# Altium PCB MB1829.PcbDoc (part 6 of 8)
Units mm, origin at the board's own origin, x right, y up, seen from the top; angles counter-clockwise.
Board outline 90 x 110 mm, 6 copper layers (Top Layer, Signal Layer 1, Signal Layer 2, Signal Layer 3, Signal Layer 4, Bottom Layer), stack 1.578 mm thick; 466 components, 354 nets, 2058 pads, 1522 vias.
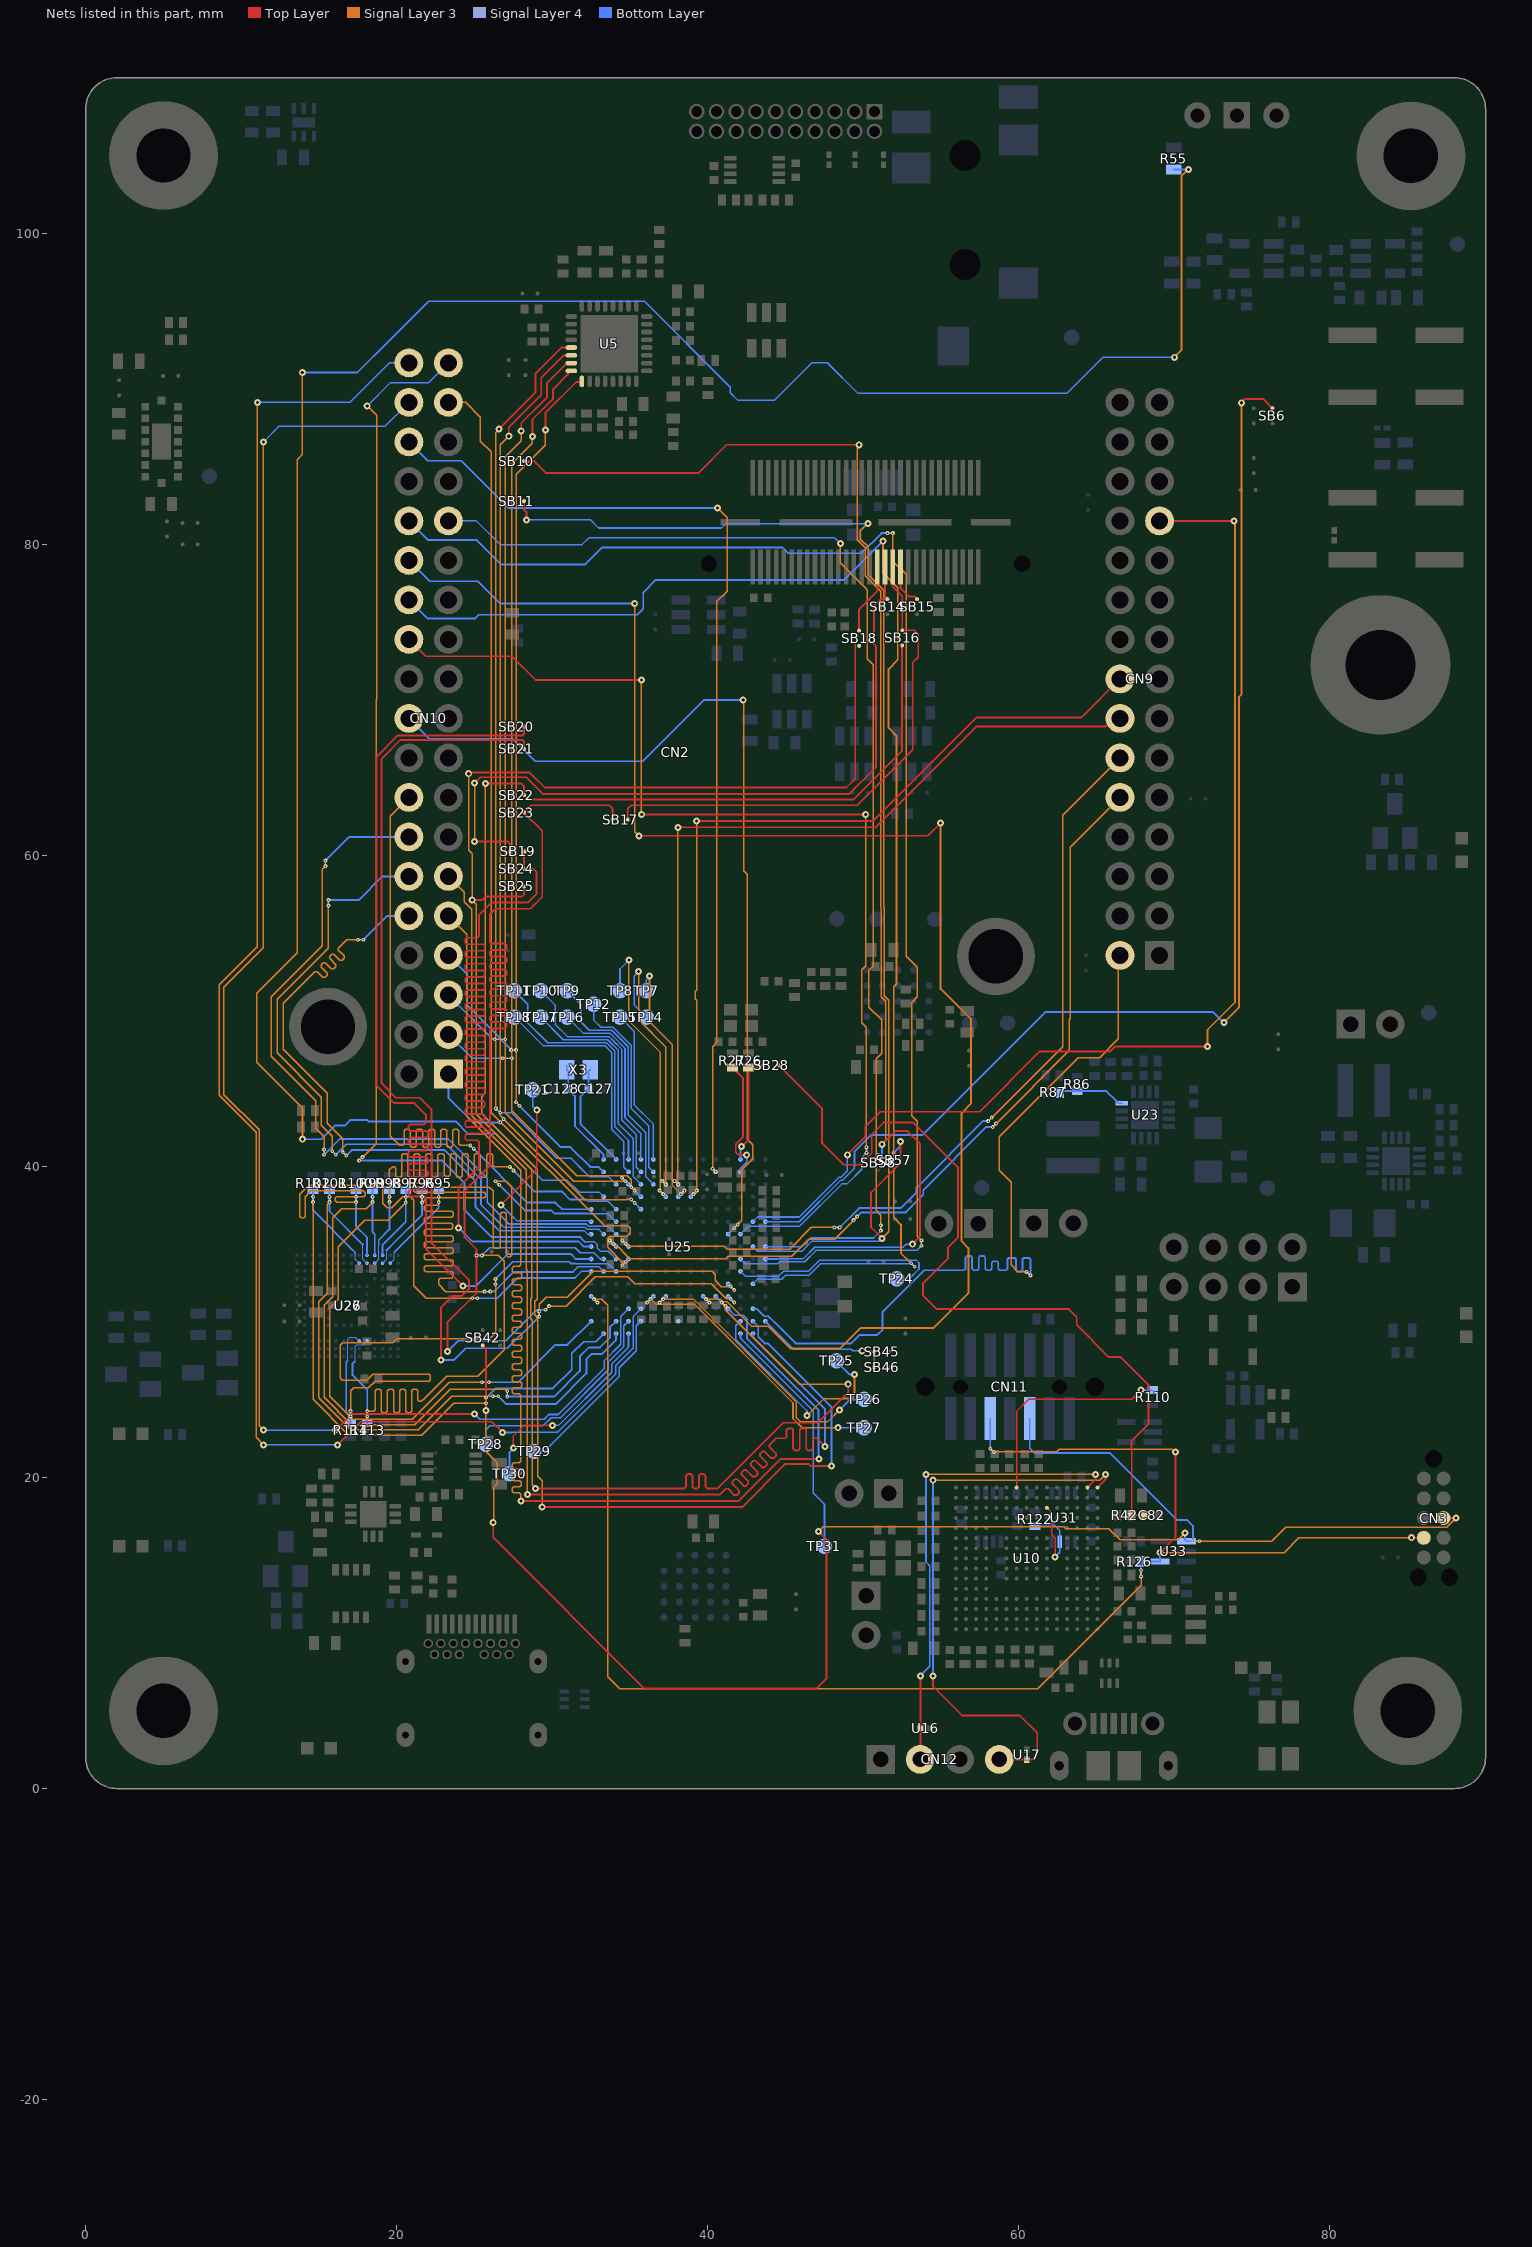
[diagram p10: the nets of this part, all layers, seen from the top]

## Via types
v1: diameter 0.45, hole 0.2, Top Layer to Bottom Layer, tented both sides, 1062 vias
v2: diameter 0.25, hole 0.1, Signal Layer 4 to Bottom Layer, tented both sides, 274 vias
v3: diameter 0.25, hole 0.1, Signal Layer 3 to Signal Layer 4, tented both sides, 119 vias
v4: diameter 0.25, hole 0.1, Top Layer to Signal Layer 1, tented both sides, 47 vias
v5: diameter 0.25, hole 0.1, Signal Layer 1 to Signal Layer 2, tented both sides, 20 vias

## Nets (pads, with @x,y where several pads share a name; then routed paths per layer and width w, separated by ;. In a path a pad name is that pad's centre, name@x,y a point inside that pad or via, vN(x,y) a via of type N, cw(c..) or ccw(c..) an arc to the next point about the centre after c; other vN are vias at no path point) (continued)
PB12: SB21.1 U25.M11 | length 76.1
  Top Layer w0.12: v1(22.85,27.55) 22.85,30.933 23.592,31.675 24.175,31.675 24.65,32.15 24.65,32.675 22.225,35.1 22.225,43.67 21.476,44.419 19.943,44.419 19.025,45.338 19.025,66.21 20.24,67.425 28.075,67.425 28.175,67.325 SB21.1@28.175,66.85
  Signal Layer 3 w0.09: v3(29.15,30.675) 29.15,31.15 29.6,31.6 30.975,31.6 32.625,33.25 40.275,33.25 40.475,33.05 40.475,32.675 40.875,32.275 v3(41.475,32.275)
  Signal Layer 4 w0.1: v2(29.15,30.35) v3@29.15,30.683 ; v3(41.475,32.275) v2(41.7,32.05)
  Bottom Layer w0.12: v1(22.85,27.55) 23.675,27.55 24.252,28.128 ; 24.255,28.125 24.445,28.315 27.115,28.315 v2(29.15,30.35) ; U25.M11@41.3,32.45 v2(41.7,32.05)
PB13: SB17.2 SB23.1 U25.M12 | length 81.3
  Top Layer w0.12: v1(23.25,28.1) 23.25,29.97 25.125,31.845 25.125,34.675 24.36,35.44 24.36,38.449 25.995,40.084 25.995,47.47 25.995,48.288 25.995,48.768 26.1,48.873 26.96,48.873 27.065,48.978 27.065,49.188 26.96,49.293 26.098,49.293 25.993,49.398 25.993,49.608 26.098,49.713 26.96,49.713 27.065,49.818 27.065,50.028 26.96,50.133 26.098,50.133 25.993,50.238 25.993,50.448 26.098,50.553 26.96,50.553 27.065,50.658 27.065,50.868 26.96,50.973 26.098,50.973 25.993,51.078 25.993,51.288 26.098,51.393 26.96,51.393 27.065,51.498 27.065,51.708 26.96,51.813 26.098,51.813 25.993,51.918 25.993,52.128 26.098,52.233 26.96,52.233 27.065,52.338 27.065,52.548 26.96,52.653 26.098,52.653 25.993,52.758 25.993,52.968 26.098,53.073 26.96,53.073 27.065,53.178 27.065,53.388 26.96,53.493 26.098,53.493 25.993,53.598 25.993,53.808 26.098,53.913 26.96,53.913 27.065,54.018 27.065,54.228 26.96,54.333 26.1,54.333 25.995,54.438 25.995,54.847 25.995,56.21 26.351,56.566 28.591,56.566 29.35,57.325 29.35,61.575 SB23.1@28.175,62.75 28.65,63.225 33.65,63.225 33.875,63 SB17.2@33.875,62.3
  Signal Layer 3 w0.09: v3(29.794,31.024) 30.899,31.024 32.775,32.9 34.85,32.9 35.3,32.45 40.23,32.45 41.18,31.5 41.45,31.5 v3(41.475,31.475)
  Signal Layer 4 w0.1: v2(29.556,30.787) v3(29.794,31.024) ; v3(41.475,31.475) v2(41.7,31.25)
  Bottom Layer w0.12: v1(23.25,28.1) 23.94,28.79 27,28.79 28.997,30.787 v2(29.556,30.787) ; U25.M12@41.3,31.65 v2(41.7,31.25)
PB14: CN9.2 U25.P13 | length 54.6
  Signal Layer 3 w0.09: v3(60.49,33.225) 59.935,33.225 59.495,33.665 59.495,38.985 58.725,39.755 58.725,41.91 63.805,46.99 65.185,46.99 66.4,48.205 66.4,53.464 CN9.2@66.5,53.564
  Signal Layer 4 w0.1: v3(60.49,33.225) 60.502,33.225 60.727,33 v2(60.74,33)
  Bottom Layer w0.1: U25.P13@42.9,30.85 43.15,30.85 43.625,30.375 43.89,30.375 44.29,29.975 44.29,29.97
  Bottom Layer w0.12: 44.29,29.97 45.64,28.62 49.22,28.62 49.77,29.17 50.895,29.17 51.235,29.51 51.235,30.62 ; 51.227,30.628 53.925,33.325 56.41,33.325 56.47,33.325 56.575,33.43 56.575,34.145 56.68,34.25 56.89,34.25 56.995,34.145 56.995,33.427 57.1,33.322 57.31,33.322 57.415,33.427 57.415,34.145 57.52,34.25 57.73,34.25 57.835,34.145 57.835,33.427 57.94,33.322 58.15,33.322 58.255,33.427 58.255,33.8 58.36,33.905 58.57,33.905 58.675,33.8 58.675,33.43 58.78,33.325 59.061,33.325 59.16,33.325 59.27,33.435 59.27,34.04 59.345,34.115 59.73,34.115 59.805,34.04 59.805,33.335 59.885,33.255 60.17,33.255 60.24,33.325 60.24,34.04 60.315,34.115 60.655,34.115 60.74,34.03 v2(60.74,33)
PB15: SB45.2 SB46.2 U25.R14 | length 8.8
  Top Layer w0.12: v1(49.925,28.15) 50.65,28.15 SB45.2@50.7,28.1 SB46.2@50.7,27.075
  Bottom Layer w0.12: U25.R14@43.7,30.05 45.5,28.25 49.225,28.25 49.325,28.15 v1(49.925,28.15)
PC4: SB6.1 U25.R6 | length 78.6
  Top Layer w0.12: v1(74.31,89.1) 74.56,89.35 75.7,89.35 SB6.1@76.3,88.75
  Signal Layer 3 w0.12: v1(73.175,49.249) 74.14,50.214 74.14,70.179 74.31,70.349 v1(74.31,89.1)
  Bottom Layer w0.1: U25.R6@43.7,36.45 45.875,36.45 48.525,39.1 48.638,39.1 49.425,39.887 49.425,40.025
  Bottom Layer w0.12: 49.425,40.025 49.425,40.95 50.506,42.031 53.806,42.031 61.7,49.925 72.499,49.925 v1(73.175,49.249)
PC5: CN9.23 U25.P6 | length 74.2
  Top Layer w0.12: v1(48.975,40.75) 50.125,41.9 50.125,42.55 51.093,43.518 57.468,43.518 61.348,47.398 65.884,47.398 66.207,47.721 v1(72.125,47.721) ; CN9.23@69.04,81.504 v1(73.825,81.504)
  Signal Layer 3 w0.12: v1(72.125,47.721) 72.125,48.781 73.885,50.541 73.885,81.444 v1(73.825,81.504)
  Bottom Layer w0.1: U25.P6@42.9,36.45 43.2,36.75 45.875,36.75 48.425,39.3 48.555,39.3 48.975,39.72 v1(48.975,40.75)
PC14-OSC32_IN: C128.1 U25.B1 X3.2 | length 7
  Bottom Layer w0.12: X3.2@30.925,46.5 X3.2@30.925,46.225 31.025,46.125 31.025,44.95 31.45,44.525 31.45,42.6 33.3,40.75 U25.B1@33.3,40.45
PC15-OSC32_OUT: C127.1 U25.C1 X3.1 | length 7
  Bottom Layer w0.12: X3.1@32.425,46.225 32.325,46.125 C127.1@32.325,45 31.81,44.485 31.81,42.749 34.1,40.459 U25.C1@34.1,40.45
PD0: CN10.35 U25.D9 | length 64.4
  Signal Layer 3 w0.09: CN10.35@23.32,89.124 24.426,89.124 25.375,88.175 25.375,86.638 26.075,85.938 26.075,43.468 33.368,36.175 34.85,36.175 35,36.025 35,35.7 34.8,35.5 33.7,35.5 33.55,35.35 33.55,34.8 34.475,33.875 v3(34.725,33.875)
  Signal Layer 4 w0.1: v2(34.5,33.65) v3(34.725,33.875)
  Bottom Layer w0.12: v2(34.5,33.65) U25.D9@34.9,34.05
PD1: CN10.37 U25.C9 | length 75.9
  Signal Layer 3 w0.09: v3(17.8,40.6) 18.666,41.466 18.666,41.539 ; v1(18.1,88.9) 18.7,88.3 18.7,70.04 18.665,70.005 18.665,41.54
  Signal Layer 4 w0.1: v2(17.575,40.375) v3(17.8,40.6)
  Bottom Layer w0.1: v1(18.1,88.9) 19.6,90.4 22.056,90.4 CN10.37@23.32,91.664 ; 32.125,35.15 32.717,35.15 32.875,34.992 32.875,34.775 33.1,34.55 33.6,34.55 U25.C9@34.1,34.05
  Bottom Layer w0.12: v2(17.575,40.375) 22.925,40.375 24.345,38.955 24.345,37.215 26.1,35.46 31.805,35.46 32.125,35.14
PD3: SB20.1 U25.A9 | length 70.2
  Top Layer w0.12: v1(24.25,32.325) 21.875,34.7 21.875,37.914 21.875,37.974 21.77,38.079 20.856,38.079 20.751,38.184 20.751,38.394 20.856,38.499 21.9,38.499 22.005,38.604 22.005,38.814 21.9,38.919 20.856,38.919 20.751,39.024 20.751,39.234 20.856,39.339 21.9,39.339 22.005,39.444 22.005,39.654 21.9,39.759 20.856,39.759 20.751,39.864 20.751,40.074 20.856,40.179 21.9,40.179 22.005,40.284 22.005,40.494 21.9,40.599 20.856,40.599 20.751,40.704 20.751,40.914 20.856,41.019 21.9,41.019 22.005,41.124 22.005,41.334 21.9,41.439 20.856,41.439 20.751,41.544 20.751,41.754 20.856,41.859 21.9,41.859 22.005,41.964 22.005,42.174 21.9,42.279 20.856,42.279 20.751,42.384 20.751,42.594 20.856,42.699 21.77,42.699 21.875,42.804 21.875,43.335 21.135,44.075 19.825,44.075 18.7,45.2 18.7,66.355 20.064,67.719 28.094,67.719 28.175,67.8 SB20.1@28.175,68.275
  Bottom Layer w0.12: v1(24.25,32.325) 25.1,32.325 27.15,34.375 31.175,34.375 31.5,34.05 U25.A9@32.5,34.05
PD4: SB19.2 SB24.1 U25.A8 | length 72.8
  Top Layer w0.12: v1(23.975,36.05) 23.975,38.65 25.275,39.95 25.275,41.523 25.275,41.583 25.17,41.688 24.505,41.688 24.4,41.793 24.4,42.003 24.505,42.108 25.55,42.108 25.655,42.213 25.655,42.423 25.55,42.528 24.505,42.528 24.4,42.633 24.4,42.843 24.505,42.948 25.55,42.948 25.655,43.053 25.655,43.263 25.55,43.368 24.505,43.368 24.4,43.473 24.4,43.683 24.505,43.788 25.55,43.788 25.655,43.893 25.655,44.103 25.55,44.208 24.505,44.208 24.4,44.313 24.4,44.523 24.505,44.628 25.55,44.628 25.655,44.733 25.655,44.943 25.55,45.048 24.51,45.048 24.405,45.153 24.405,45.363 24.51,45.468 25.55,45.468 25.655,45.573 25.655,45.783 25.55,45.888 24.51,45.888 24.405,45.993 24.405,46.203 24.51,46.308 25.55,46.308 25.655,46.413 25.655,46.623 25.55,46.728 24.51,46.728 24.405,46.833 24.405,47.043 24.51,47.148 25.55,47.148 25.655,47.253 25.655,47.463 25.55,47.568 24.505,47.568 24.4,47.673 24.4,47.883 24.505,47.988 25.55,47.988 25.655,48.093 25.655,48.303 25.55,48.408 24.51,48.408 24.405,48.513 24.405,48.723 24.51,48.828 25.55,48.828 25.655,48.933 25.655,49.143 25.55,49.248 24.505,49.248 24.4,49.353 24.4,49.563 24.505,49.668 25.55,49.668 25.655,49.773 25.655,49.983 25.55,50.088 24.505,50.088 24.4,50.193 24.4,50.403 24.505,50.508 25.55,50.508 25.655,50.613 25.655,50.823 25.55,50.928 24.51,50.928 24.405,51.033 24.405,51.243 24.51,51.348 25.55,51.348 25.655,51.453 25.655,51.663 25.55,51.768 24.505,51.768 24.4,51.873 24.4,52.083 24.505,52.188 25.55,52.188 25.655,52.293 25.655,52.503 25.55,52.608 24.505,52.608 24.4,52.713 24.4,52.923 24.505,53.028 25.55,53.028 25.655,53.133 25.655,53.343 25.55,53.448 24.51,53.448 24.405,53.553 24.405,53.763 24.51,53.868 25.55,53.868 25.655,53.973 25.655,54.183 25.55,54.288 24.505,54.288 24.4,54.393 24.4,54.603 24.505,54.708 25.17,54.708 25.275,54.813 25.275,55.23 25.275,56.15 26.1,56.975 28.45,56.975 28.975,57.5 28.975,58.95 28.8,59.125 SB24.1@28.175,59.125 SB19.2@28.175,60.25
  Bottom Layer w0.12: v1(23.975,36.05) 24.85,35.175 31.7,35.175 32.025,34.85 U25.A8@32.5,34.85
PD6: CN9.10 U25.C8 | length 53.9
  Signal Layer 3 w0.09: v3(33.925,35.025) 34.039,35.025 34.989,34.075 41.175,34.075 41.325,34.225 45.392,34.225 46.495,35.328 48.153,35.328 v3(49.375,36.55) ; v3(58.535,42.76) 63.23,47.455 63.23,49.42 63.305,49.495 63.305,60.53 63.47,60.695 ; 63.47,60.695 CN9.10@66.5,63.724
  Signal Layer 4 w0.1: v2(33.7,35.25) v3(33.925,35.025) ; v3(49.375,36.55) v2(49.6,36.775) ; v2(58.315,42.53) 58.315,42.535 58.535,42.755 v3(58.535,42.76)
  Bottom Layer w0.12: v2(33.7,35.25) U25.C8@34.1,34.85 ; v2(49.6,36.775) 49.875,37.05 52.73,37.05 53.85,38.17 53.85,38.48 57.91,42.54 58.305,42.54 v2(58.315,42.53)
PD7: CN9.12 U25.D8 | length 54.8
  Signal Layer 3 w0.09: v3(34.725,35.025) 34.875,34.875 41.05,34.875 41.25,34.675 45.263,34.675 46.663,36.075 v3(48.127,36.075) ; v3(58.255,43.14) 62.82,47.705 62.82,62.584 CN9.12@66.5,66.264
  Signal Layer 4 w0.1: v2(34.5,35.25) v3(34.725,35.025) ; v3(48.127,36.075) v2(48.475,36.075) ; v2(58.02,42.92) 58.027,42.92 58.247,43.14 v3(58.255,43.14)
  Bottom Layer w0.12: v2(34.5,35.25) U25.D8@34.9,34.85 ; v2(48.475,36.075) 49.725,37.325 52.405,37.325 53.42,38.34 53.42,38.645 57.7,42.925 58.015,42.925 v2(58.02,42.92)
PD9: CN10.11 U25.P15 | length 83.8
  Top Layer w0.12: v1(28.4,18.9) 40.775,18.9 40.812,18.937 41.152,19.277 41.3,19.277 41.709,18.868 41.858,18.868 42.006,19.016 42.006,19.165 41.58,19.591 41.58,19.74 41.728,19.888 41.877,19.888 42.303,19.462 42.452,19.462 42.6,19.61 42.6,19.759 42.174,20.185 42.174,20.334 42.322,20.482 42.471,20.482 42.897,20.056 43.046,20.056 43.194,20.204 43.194,20.353 42.768,20.779 42.768,20.928 42.916,21.076 43.065,21.076 43.491,20.65 43.64,20.65 43.788,20.798 43.788,20.947 43.362,21.373 43.362,21.522 43.51,21.67 43.659,21.67 44.085,21.244 44.234,21.244 44.382,21.392 44.382,21.541 43.973,21.95 43.973,22.098 44.217,22.342 44.4,22.525 44.9,22.525 44.96,22.525 45.065,22.63 45.065,23.057 45.17,23.162 45.38,23.162 45.485,23.057 45.485,21.846 45.59,21.741 45.8,21.741 45.905,21.846 45.905,23.057 46.01,23.162 46.22,23.162 46.325,23.057 46.325,21.846 46.43,21.741 46.64,21.741 46.745,21.846 46.745,22.42 46.85,22.525 47,22.525 47.075,22.45 v1(47.525,22)
  Signal Layer 3 w0.09: CN10.11@23.32,58.644 24.35,57.614 24.35,57.013 24.825,56.538 24.825,43.275 27.425,40.675 28.325,39.775 28.325,33.392 28.384,33.333 28.384,18.916 v1(28.4,18.9)
  Bottom Layer w0.12: U25.P15@42.9,29.25 42.9,29.05 47.525,24.425 v1(47.525,22)
PD10: SB16.2 SB22.1 U25.P14 | length 115.3
  Top Layer w0.12: v1(25.7,64.625) 28,64.625 28.175,64.45 SB22.1@28.175,63.875 28.45,63.6 49.375,63.6 52.475,66.7 52.475,73.471 SB16.2@52.5,73.496 ; v1(29.35,18.1) 42.2,18.1 44.975,20.875 46.475,20.875 46.6,20.75 v1(47.95,20.75)
  Signal Layer 3 w0.09: v1(25.7,64.625) 25.7,44.725 25.45,44.475 25.45,43.4 29.025,39.825 29.025,31.475 28.875,31.325 28.875,30.45 29.075,30.25 29.075,20.075 29.35,19.8 v1(29.35,18.1)
  Bottom Layer w0.12: U25.P14@42.9,30.05 43.24,29.71 43.24,29.059 43.684,28.615 43.87,28.615 47.945,24.54 47.945,24.135 ; v1(47.95,20.75) 47.95,24.135
PD11: SB18.2 SB25.1 U25.L12 | length 123.4
  Top Layer w0.12: v1(24.625,65.25) 24.688,65.313 24.849,65.313 24.86,65.325 28.55,65.325 29.51,64.365 48.915,64.365 49.475,64.925 49.475,73.651 ; v1(24.85,57.125) 25.475,57.125 25.701,57.351 28.051,57.351 28.175,57.475 SB25.1@28.175,58 ; v1(28.925,19.3) 38.425,19.3 38.485,19.3 38.59,19.405 38.59,20.114 38.695,20.219 38.905,20.219 39.01,20.114 39.01,19.394 39.115,19.289 39.325,19.289 39.43,19.394 39.43,20.114 39.535,20.219 39.745,20.219 39.85,20.114 39.85,19.405 39.955,19.3 40.637,19.3 44.862,23.525 47.066,23.525 49.025,25.484 v1(49.025,26)
  Signal Layer 3 w0.09: v1(24.625,65.25) 24.625,60.325 24.85,60.1 v1(24.85,57.125) 25.125,56.85 25.125,43.35 28.675,39.8 28.675,31.555 28.625,31.505 28.625,30.2 28.7,30.125 28.7,19.525 v1(28.925,19.3) ; v3(41.125,31.025) 41.125,30.779 45.904,26 v1(49.025,26)
  Signal Layer 4 w0.1: v2(40.9,31.25) v3(41.125,31.025)
  Bottom Layer w0.12: U25.L12@40.5,31.65 v2(40.9,31.25)
PD12: CN10.9 U25.M13 | length 85.7
  Top Layer w0.12: v1(27.975,18.5) 41.975,18.5 44.675,21.2 v1(47.15,21.2)
  Signal Layer 3 w0.09: CN10.9@23.32,56.104 24.5,54.924 24.5,43.225 27.975,39.75 27.975,34.1 27.975,33.665 27.878,33.567 27.523,33.567 27.425,33.47 27.425,33.275 27.523,33.177 27.938,33.177 28.035,33.08 28.035,32.885 27.938,32.787 27.523,32.787 27.425,32.69 27.425,32.495 27.523,32.397 27.938,32.397 28.035,32.3 28.035,32.105 27.938,32.007 27.523,32.007 27.425,31.91 27.425,31.715 27.523,31.617 27.938,31.617 28.035,31.52 28.035,31.325 27.938,31.227 27.523,31.227 27.425,31.13 27.425,30.935 27.523,30.837 27.938,30.837 28.035,30.74 28.035,30.545 27.938,30.447 27.523,30.447 27.425,30.35 27.425,30.155 27.523,30.057 27.938,30.057 28.035,29.96 28.035,29.765 27.938,29.667 27.523,29.667 27.425,29.57 27.425,29.375 27.523,29.277 27.938,29.277 28.035,29.18 28.035,28.985 27.938,28.887 27.523,28.887 27.425,28.79 27.425,28.595 27.523,28.497 27.938,28.497 28.035,28.4 28.035,28.205 27.938,28.108 27.523,28.108 27.425,28.01 27.425,27.815 27.523,27.718 27.938,27.718 28.035,27.62 28.035,27.425 27.938,27.328 27.523,27.328 27.425,27.23 27.425,27.035 27.523,26.938 27.938,26.938 28.035,26.84 28.035,26.645 27.938,26.548 27.523,26.548 27.425,26.45 27.425,26.255 27.523,26.158 27.938,26.158 28.035,26.06 28.035,25.865 27.938,25.768 27.523,25.768 27.425,25.67 27.425,25.475 27.523,25.378 27.878,25.378 27.975,25.28 27.975,24.909 27.975,21.2 27.975,21.057 27.878,20.959 27.523,20.959 27.425,20.862 27.425,20.667 27.523,20.569 27.892,20.569 27.989,20.472 27.989,20.277 27.892,20.179 27.523,20.179 27.425,20.082 27.425,19.887 27.523,19.789 27.892,19.789 27.989,19.692 27.989,19.497 27.892,19.399 27.523,19.399 27.425,19.302 27.425,19.107 27.523,19.009 27.878,19.009 27.975,18.912 27.975,18.867 v1(27.975,18.5)
  Bottom Layer w0.12: U25.M13@41.3,30.85 41.714,30.436 42.264,30.436 42.525,30.175 42.525,28.925 47.125,24.325 47.125,21.225 v1(47.15,21.2)
PD13: TP25.1 U25.N14 | length 14.8
  Signal Layer 3 w0.1: v1(46.375,23.975) 47.475,25.075 48.775,25.075
  Signal Layer 3 w0.12: 48.775,25.075 49.246,25.075 49.425,25.254 v1(49.425,26.627)
  Bottom Layer w0.1: U25.N14@42.1,30.05 41.8,29.75 41.8,28.85 46.375,24.275 v1(46.375,23.975) ; TP25.1@48.275,27.725 TP25.1@48.422,27.578
  Bottom Layer w0.12: TP25.1@48.275,27.5 48.275,27.452 49.1,26.627 v1(49.425,26.627)
PD14: TP31.1 U25.N15 | length 15.9
  Bottom Layer w0.1: U25.N15@42.1,29.25 42.1,28.95 46.775,24.275 46.775,19 47.5,18.275 47.5,16.37 TP31.1@47.5,15.575
PD15: CN10.28 U25.K12 | length 102.5
  Top Layer w0.12: v1(35.567,61.258) 54.138,61.258 v1(54.962,62.082)
  Signal Layer 3 w0.1: v3(39.875,31.475) 40.8,31.475 40.975,31.3 41.239,31.3 42.814,29.725 43.875,29.725
  Signal Layer 3 w0.12: v1@35.3,76.202 35.3,61.525 v1(35.567,61.258) ; 43.875,29.725 45.3,28.3 48.5,28.3 49.82,29.62 54.52,29.62 56.75,31.85 56.75,34.75 56.31,35.19 56.31,43.435 56.925,44.05 56.925,49.45 54.962,51.413 v1(54.962,62.082)
  Signal Layer 4 w0.1: v3(39.875,31.475) v2(40.1,31.25)
  Bottom Layer w0.12: CN10.28@20.78,78.964 22.119,77.625 25.2,77.625 26.62,76.205 35.295,76.205 v1@35.3,76.2 ; U25.K12@39.7,31.65 v2(40.1,31.25)
  other v1: 35.298,76.202
PE2: CN10.1 U5.30 U25.E5 | length 68.5
  Top Layer w0.12: v1(27.2,86.95) 27.2,87.525 29.291,89.616 29.291,90.716 29.425,90.85 30.725,92.15 U5.30@31.225,92.15
  Signal Layer 3 w0.09: v1(27.2,86.95) 26.645,86.395 26.645,43.28 v3(26.875,43.05) 32.075,37.85 34.8,37.85 34.825,37.875 v3(35.075,37.875) ; v3@35.075,37.85 v3@35.1,37.85
  Signal Layer 4 w0.1: v2(26.65,42.825) v3(26.875,43.05) ; v3(35.075,37.875) v2(35.3,37.65)
  Bottom Layer w0.12: CN10.1@23.32,45.944 23.32,44.42 24.915,42.825 v2(26.65,42.825) ; v2(35.3,37.65) U25.E5@35.7,37.25
PE4: CN10.7 U5.1 U25.B2 | length 63.9
  Top Layer w0.12: v1(29.55,87.35) 29.556,87.356 29.556,88.446 31.556,90.446 31.871,90.446 U5.1@31.9,90.475
  Signal Layer 3 w0.09: v3(27.675,44.125) 27.681,44.131 27.681,47.469 v3(27.675,47.475) 27.681,47.481 27.681,84.496 29.556,86.371 29.556,87.344 v1(29.55,87.35)
  Signal Layer 4 w0.1: v2(27.35,47.475) 27.365,47.46 27.66,47.46 v3(27.675,47.475) ; v3(27.675,44.125) 27.675,44.109 27.884,43.9 v2(27.9,43.9)
  Bottom Layer w0.12: CN10.7@23.32,53.564 24.525,52.359 24.525,50.353 26.585,48.293 26.585,48.268 27.35,47.503 v2(27.35,47.475) ; v2(27.9,43.9) 27.9,43.877 30.531,41.246 31.16,41.246 32.435,39.971 32.956,39.971 33.277,39.65 U25.B2@33.3,39.65
PE5: CN10.5 U5.31 U25.D3 | length 65.5
  Top Layer w0.12: v1(28,87.275) 28,87.8 29.665,89.465 29.665,90.39 30.849,91.574 30.875,91.574 30.951,91.65 U5.31@31.225,91.65
  Signal Layer 3 w0.09: v1(28,87.275) 28,86.65 26.975,85.625 v3(26.975,48.175) 26.975,43.45 31.4,39.025 31.425,39.05 v3(34.7,39.05)
  Signal Layer 4 w0.1: v2(26.3,48.175) v3(26.975,48.175) ; v2(34.475,39.275) v3(34.7,39.05)
  Bottom Layer w0.12: CN10.5@23.32,51.024 26.144,48.2 26.275,48.2 v2(26.3,48.175) ; v2(34.475,39.275) U25.D3@34.9,38.85
PE6: CN10.3 U5.32 U25.E4 | length 64.8
  Top Layer w0.12: v1(28.725,86.925) 28.725,88.025 30.053,89.353 30.053,89.978 30.999,90.924 30.999,91.067 31.082,91.15 U5.32@31.225,91.15
  Signal Layer 3 w0.09: v1(28.725,86.925) 28.725,86.5 27.4,85.175 27.4,43.575 31.575,39.4 34.825,39.4 35.075,39.15 v3(35.075,38.675)
  Signal Layer 4 w0.1: v2(26.8,46.96) v3(27.4,46.96) ; v3(35.075,38.675) v2(35.3,38.45)
  Bottom Layer w0.12: CN10.3@23.32,48.484 24.844,46.96 v2(26.8,46.96) ; v2(35.3,38.45) U25.E4@35.7,38.05
PE7: CN10.30 U25.N9 | length 92.5
  Signal Layer 3 w0.09: v3(51.9,80.725) 51.9,78.924 52.75,78.074 52.75,53.525 53.475,52.8 53.475,50.901 53.1,50.526 53.1,43.25 53.45,42.9 53.45,35.523 v3(53.725,35.248)
  Signal Layer 4 w0.1: v2(51.552,80.725) v3(51.9,80.725) ; v2(53.725,34.9) v3(53.725,35.248)
  Bottom Layer w0.1: U25.N9@42.1,34.05 42.4,33.75 44.484,33.75 44.609,33.875 46.227,33.875 46.952,34.6 50.879,34.6 53.425,34.6 v2(53.725,34.9)
  Bottom Layer w0.12: CN10.30@20.78,81.504 22.009,80.275 25.15,80.275 26.725,78.7 32.1,78.7 33.2,79.8 44.8,79.8 45.175,79.425 49.875,79.425 51.175,80.725 v2(51.552,80.725)
PE11: CN10.26 U25.P11 | length 92.8
  Signal Layer 3 w0.12: v1(51.25,80.2) 51.25,78.175 52.21,77.215 52.21,72.566 51.625,71.981 51.625,68.2 52.125,67.7 52.125,51.725 51.95,51.55 51.95,36.725 52.415,36.26 52.415,34.435 v3(53.075,33.775)
  Signal Layer 4 w0.1: v3(53.075,33.775) v2(53.3,33.55)
  Bottom Layer w0.1: U25.P11@42.9,32.45 43.2,32.75 44.75,32.75 45,33 46.5,33 47.255,33.755 53.095,33.755 v2(53.3,33.55)
  Bottom Layer w0.12: CN10.26@20.78,76.424 21.979,75.225 25.025,75.225 25.275,75.475 35.47,75.475 35.85,75.855 35.85,76.9 36.66,77.71 48.76,77.71 v1(51.25,80.2)
PE15: TP24.1 U25.N10 | length 14.2
  Bottom Layer w0.1: U25.N10@42.1,33.25 42.4,32.95 44.55,32.95 44.85,33.25 46.45,33.25 47.155,33.955 48.775,33.955 53.42,33.955 53.575,33.8 53.575,33.4 52.949,32.774 TP24.1@52.152,32.774
PF0: CN9.14 U25.H3 | length 54.9
  Top Layer w0.12: v1@38.1,61.807 50.782,61.807 57.25,68.275 65.566,68.275 66.095,68.804 CN9.14@66.5,68.804
  Signal Layer 3 w0.09: v1(38.075,61.8) 38.08,61.795 38.08,45.925 38.08,38.87 v3(38.1,38.85)
  Signal Layer 4 w0.1: v2(37.857,39.065) 37.871,39.065 38.086,38.85 v3(38.1,38.85)
  Bottom Layer w0.1: v2(37.857,39.065) 37.871,39.065 38.086,38.85 v3(38.1,38.85)
PF1: CN9.16 U25.J4 | length 56
  Top Layer w0.12: v1(39.275,62.221) 50.646,62.221 57.3,68.875 64.031,68.875 CN9.16@66.5,71.344
  Signal Layer 3 w0.09: v3(39.075,38.225) 39.275,38.425 39.275,45.925 39.275,50.698 39.197,50.776 39.197,51.264 39.275,51.342 v1(39.275,62.221)
  Signal Layer 4 w0.1: v3(39.075,38.225) v2(39.3,38.45)
  Bottom Layer w0.12: U25.J4@38.9,38.05 v2(39.3,38.45)
PF5: CN10.34 U25.L2 | length 65.6
  Signal Layer 3 w0.09: v3(40.5,39.65) 40.308,39.842 40.308,45.925 40.308,47.707 40.575,47.975 40.575,76.325 41.238,76.988 41.238,81.712 v1(40.625,82.325)
  Signal Layer 4 w0.1: v2(40.3,39.85) v3(40.5,39.65)
  Bottom Layer w0.1: v2(40.3,39.85) v3(40.5,39.65)
  Bottom Layer w0.12: CN10.34@20.78,86.584 21.989,85.375 24.148,85.375 27.198,82.325 v1(40.625,82.325)
PF12: CN10.24 U25.N7 | length 71.9
  Top Layer w0.12: CN10.24@20.78,73.884 21.865,72.799 27.401,72.799 28.925,71.275 v1(35.725,71.275) v1@35.725,71.135 ; v1(35.75,62.625) v1(50.15,62.625)
  Signal Layer 3 w0.09: v1(35.725,71.275) 35.725,62.65 v1(35.75,62.625) ; v1(50.15,62.625) 50.15,52.9 49.9,52.65 49.9,49.25 50.2,48.95 v3(50.2,41.223)
  Signal Layer 4 w0.1: v2(50.2,40.875) v3(50.2,41.223)
  Bottom Layer w0.1: U25.N7@42.1,35.65 42.6,36.15 45.892,36.15 48.617,38.875 48.95,38.875 49.9,39.825 49.9,40.575 v2(50.2,40.875)
PF13: CN10.20 U25.M7 | length 59.5
  Signal Layer 3 w0.09: v3(41.925,36.275) 42.175,36.525 42.175,39.794 42.875,40.494 42.875,41.4 42.525,41.75 42.525,58.775 42.3,59 42.3,69.975 v1(42.275,70)
  Signal Layer 4 w0.1: v2(41.7,36.05) v3(41.925,36.275)
  Bottom Layer w0.12: CN10.20@20.78,68.804 22.085,67.499 27.46,67.499 28.909,66.05 35.807,66.05 39.757,70 v1(42.275,70) ; U25.M7@41.3,35.65 v2(41.7,36.05)
PF14: CN10.29 U25.R8 | length 79.8
  Signal Layer 3 w0.09: v1(48.525,80.05) 48.525,78.8 50.25,77.075 50.25,72.64 50.625,72.265 50.625,52.875 50.355,52.605 50.355,50.245 51.175,49.425 51.175,47.275 50.825,46.925 50.825,37.175 51.125,36.875 v3(51.125,36.223)
  Signal Layer 4 w0.1: v2(51.125,35.875) v3(51.125,36.223)
  Bottom Layer w0.1: CN10.29@23.32,81.504 25.121,81.504 26.645,79.98 31.912,79.98 32.357,80.425 48.15,80.425 v1(48.525,80.05) ; U25.R8@43.7,34.85 46.07,34.85 46.62,35.4 50.65,35.4 v2(51.125,35.875)
PF15: SB11.1 SB57.1 U25.P8 | length 87.6
  Top Layer w0.12: SB11.1@28.175,82.775 28.175,82.225 28.35,82.05 v1(28.35,81.575) ; v1(51.2,35.375) 50.5,36.075 50.5,38.325 52.375,40.2 v1(52.375,41.6)
  Signal Layer 3 w0.09: v1(50.302,81.329) 50.256,81.329 49.809,80.882 49.809,80.341 50.302,79.848 50.302,78.048 51.305,77.045 51.305,62.078 51.305,56.672 51.35,56.627 51.35,50.975 51.638,50.688 51.638,35.813 v1(51.2,35.375)
  Bottom Layer w0.1: v1(28.35,81.575) 32.45,81.575 32.975,81.05 40.875,81.05 41.154,81.329 v1(50.302,81.329) ; U25.P8@42.9,34.85 43.2,34.55 46.053,34.55 46.703,35.2 51.025,35.2 v1(51.2,35.375)
  Bottom Layer w0.12: SB57.1@51.95,40.877 52.358,41.285 52.358,41.583 v1(52.375,41.6)
PG0: SB10.1 SB58.2 U25.R9 | length 89.1
  Top Layer w0.12: SB10.1@28.175,85.35 28.85,85.35 29.625,84.575 39.375,84.575 41.2,86.4 v1(49.725,86.4) ; v1(51.2,41.425) 52.05,42.275 52.825,42.275 53.65,41.45 53.65,35.5 v1(53.15,35)
  Signal Layer 3 w0.09: v1(49.725,86.4) 49.725,86.303 49.6,86.178 49.6,80.281 50.112,79.769 50.112,77.969 51.038,77.044 51.115,76.966 51.115,62.157 51.115,56.593 51.16,56.548 51.16,50.896 51.448,50.609 51.448,41.673 v1(51.2,41.425)
  Bottom Layer w0.1: U25.R9@43.7,34.05 44.501,34.05 44.527,34.075 46.144,34.075 46.869,34.8 50.962,34.8 52.55,34.8 52.75,35 v1(53.15,35)
  Bottom Layer w0.12: SB58.2@50.95,40.725 50.964,40.739 51.13,40.739 51.2,40.81 v1(51.2,41.425)
PG2: TP26.1 U25.G12 | length 18.3
  Signal Layer 3 w0.1: v3(37.125,31.475) 39.077,31.475 45.675,24.877 45.675,23.875 45.975,23.575 47.7,23.575 v1(48.475,24.35)
  Signal Layer 4 w0.1: v2(36.9,31.25) v3(37.125,31.475)
  Bottom Layer w0.1: v1(48.475,24.35) 48.775,24.65
  Bottom Layer w0.12: v2(36.9,31.25) U25.G12@37.3,31.65 ; 48.775,24.65 49.15,25.025 TP26.1@50.05,25.025
PG3: TP30.1 U25.D15 | length 13.5
  Top Layer w0.1: v1(27.5,21.9) 27.5,22.675 28.175,23.35 v1(30,23.35)
  Bottom Layer w0.1: v1@27.425,21.811 27.5,21.886 v1(27.5,21.9) ; v1(30,23.35) 30.4,23.35 33.825,26.775 33.825,27.3 34.9,28.375 U25.D15@34.9,29.25
  Bottom Layer w0.12: TP30.1@27.25,20.25 27.25,21.636 v1@27.425,21.811
PG4: TP27.1 U25.F12 | length 18.6
  Signal Layer 3 w0.1: v3(36.325,31.475) 36.65,31.15 39.119,31.15 45.475,24.794 45.475,23.792 46.067,23.2 v1(48.375,23.2)
  Signal Layer 4 w0.1: v2(36.1,31.25) v3(36.325,31.475)
  Bottom Layer w0.1: v1(48.375,23.2) 48.775,23.2
  Bottom Layer w0.12: v2(36.1,31.25) U25.F12@36.5,31.65 ; 48.775,23.2 TP27.1@50.05,23.2
PG5: TP29.1 U25.E14 | length 11.6
  Bottom Layer w0.1: TP29.1@28.825,21.675 29.475,21.675 34.3,26.5 34.3,27.05 35.4,28.15 35.4,29.75 U25.E14@35.7,30.05
PG6: TP28.1 U25.D14 | length 14.1
  Bottom Layer w0.1: TP28.1@25.728,22.125 25.728,23.078 25.975,23.325 29.4,23.325 29.925,23.85 30.525,23.85 33.6,26.925 33.6,27.425 34.6,28.425 34.6,29.75 U25.D14@34.9,30.05
PG7: CN10.36 U25.D13 | length 104.5
  Top Layer w0.12: v1(16.075,23.05) 17.1,24.075 v1(25,24.075)
  Signal Layer 3 w0.09: v1(11.425,23.05) 11.15,23.325 11.15,42.35 8.875,44.625 8.875,51.525 11.425,54.075 v1(11.425,86.575)
  Bottom Layer w0.1: v1(11.425,23.05) v1(16.075,23.05) ; v1(11.425,86.575) 12.45,87.6 19.256,87.6 CN10.36@20.78,89.124 ; 27.425,23.75 29.475,23.75 29.775,24.05 30.375,24.05 33.35,27.025 ; 33.35,27.05 33.353,27.053 33.353,27.528 34.4,28.575 34.4,30.35 U25.D13@34.9,30.85
  Bottom Layer w0.12: v1@24.9,24.175 25.325,23.75 27.425,23.75
PG8: CN10.38 U25.E13 | length 110
  Top Layer w0.12: v1(16.2,22.1) 17.685,23.585 26.115,23.585 v1(26.8,22.9)
  Signal Layer 3 w0.09: v1(11.035,89.124) 11.035,54.135 8.575,51.675 8.575,44.575 10.95,42.2 10.95,22.575 v1(11.425,22.1)
  Bottom Layer w0.1: v1(11.035,89.124) 16.974,89.124 19.514,91.664 CN10.38@20.78,91.664 ; v1(11.425,22.1) v1(16.2,22.1) ; 27.425,22.9 30.325,22.9 34.075,26.65 34.075,27.2 35.2,28.325 35.2,30.35 U25.E13@35.7,30.85
  Bottom Layer w0.12: v1(26.8,22.9) 27.425,22.9
PG9: CN10.10 U25.A7 | length 44.7
  Signal Layer 3 w0.09: v3(16.525,40.925) 16.525,41.775 15.525,42.775 15.525,44.7 12.7,47.525 12.7,50.491 14.427,52.218 14.735,52.526 14.872,52.526 15.246,52.152 15.384,52.152 15.521,52.29 15.521,52.428 15.13,52.819 15.13,52.957 15.268,53.095 15.406,53.095 15.797,52.704 15.935,52.704 16.073,52.842 16.073,52.98 15.682,53.371 15.682,53.509 15.82,53.647 15.958,53.647 16.349,53.255 16.487,53.255 16.625,53.393 16.625,53.531 16.251,53.904 16.251,54.042 16.504,54.296 16.784,54.575 v3@17.5,54.575
  Signal Layer 4 w0.1: v3(16.525,40.925) v2(16.75,40.7) ; v3(17.503,54.578) v2(17.85,54.578)
  Bottom Layer w0.1: 26.483,35.967 26.57,35.88 32.029,35.88 32.259,35.65 U25.A7@32.5,35.65
  Bottom Layer w0.12: v2(16.75,40.7) 17.1,41.05 23.085,41.05 25.05,39.085 25.05,37.4 26.483,35.967 ; v2(17.85,54.578) 19.377,56.104 CN10.10@20.78,56.104
PG10: CN10.12 U25.B7 | length 46
  Signal Layer 3 w0.09: v3(15.6,56.772) 15.6,54.03 12.31,50.74 12.31,47.305 15.15,44.465 15.15,42.645 15.85,41.945 v3(15.85,40.975)
  Signal Layer 4 w0.1: v3(15.6,56.772) v2(15.6,57.12) ; v3(15.85,40.975) v2(16.075,40.75)
  Bottom Layer w0.1: 26.783,36.182 26.865,36.1 32.092,36.1 32.242,35.95 33,35.95 U25.B7@33.3,35.65
  Bottom Layer w0.12: v2(15.6,57.12) 17.545,57.12 19.069,58.644 CN10.12@20.78,58.644 ; v2(16.075,40.75) 16.75,41.425 23.175,41.425 25.415,39.185 25.415,37.55 26.783,36.182
PG11: CN10.14 U25.C7 | length 50.4
  Signal Layer 3 w0.09: v3(15.325,41.098) 15.325,41.895 14.78,42.44 14.78,44.235 11.915,47.1 11.915,50.91 15.2,54.195 15.2,59.097 v3(15.415,59.312)
  Signal Layer 4 w0.1: v2(15.325,40.75) v3(15.325,41.098) ; v3(15.415,59.312) v2(15.415,59.66)
  Bottom Layer w0.1: 27.125,36.375 27.2,36.3 32.175,36.3 32.325,36.15 33.6,36.15 U25.C7@34.1,35.65
  Bottom Layer w0.12: v2(15.325,40.75) 16.34,41.765 23.305,41.765 25.815,39.255 25.815,37.685 27.125,36.375 ; v2(15.415,59.66) 16.939,61.184 CN10.14@20.78,61.184
PG12: TP21.1 U25.A6 | length 14.7
  Top Layer w0.1: 27.425,38.25 29,39.825 v1(29,43.625)
  Top Layer w0.12: v1(26.7,37.525) 27.425,38.25
  Bottom Layer w0.1: 27.425,36.8 27.725,36.5 32.45,36.5 U25.A6@32.5,36.45 ; TP21.1@28.75,44.925 28.75,43.875 v1(29,43.625)
  Bottom Layer w0.12: v1(26.7,37.525) 27.425,36.8
PG15: CN10.16 U25.A5 | length 47.4
  Signal Layer 3 w0.09: CN10.16@20.78,63.724 19.57,62.514 19.57,41.955 20.175,41.35 20.213,41.35 20.389,41.35 20.486,41.448 20.486,42.298 20.583,42.396 20.779,42.396 20.876,42.298 20.876,41.326 20.973,41.228 21.168,41.228 21.266,41.326 21.266,42.298 21.363,42.396 21.558,42.396 21.656,42.298 21.656,41.326 21.753,41.228 21.948,41.228 22.046,41.326 22.046,42.298 22.143,42.396 22.338,42.396 22.436,42.298 22.436,41.326 22.533,41.228 22.728,41.228 22.826,41.326 22.826,42.298 22.923,42.396 23.118,42.396 23.216,42.298 23.216,41.326 23.313,41.228 23.508,41.228 23.606,41.326 23.606,42.298 23.703,42.396 23.898,42.396 23.996,42.298 23.996,41.448 24.093,41.35 24.529,41.35 v3(24.725,41.35)
  Signal Layer 4 w0.1: v3(24.725,41.35) v2(24.95,41.125)
  Bottom Layer w0.12: v2(24.95,41.125) 28.4,37.675 30.2,37.675 30.625,37.25 U25.A5@32.5,37.25
PGOOD: R86.1 R87.2 U23.4 | length 4.3
  Bottom Layer w0.12: R87.2@62.647,44.766 62.722,44.841 R86.1@63.747,44.841 65.628,44.841 66.282,44.187 66.282,44.154 66.372,44.064 U23.4@66.622,44.064
PH0-OSC_IN: R26.1 SB28.2 U25.N1 | length 7.3
  Top Layer w0.12: v1(42.175,41.275) 42.625,41.725 42.625,46.237 42.512,46.35 R26.1@42.625,46.35 43.425,46.35 SB28.2@43.575,46.5
  Bottom Layer w0.12: U25.N1@42.1,40.45 v1@42.1,41.275
PH1-OSC_OUT: R27.1 U25.N2 | length 7.9
  Top Layer w0.12: R27.1@41.575,46.35 41.845,46.08 42.265,45.66 42.265,41.909 41.79,41.435 41.79,40.91 41.975,40.725 v1(42.5,40.725)
  Bottom Layer w0.12: U25.N2@42.1,39.65 42.1,39.875 42.5,40.275 v1(42.5,40.725)
PH3-BOOT0: R55.1 U25.B4 | length 150.6
  Signal Layer 3 w0.12: v1(13.925,91.05) 13.925,85.775 13.6,85.45 13.6,53.725 11,51.125 11,46.7 13.928,43.772 v1(13.928,41.75) ; v1(70,92.025) 70.45,92.475 70.45,103.65 v1(70.9,104.1)
  Bottom Layer w0.1: 19.575,93.15 22.05,95.625 35.925,95.625 41.448,90.102 41.448,89.741 41.914,89.275 44.3,89.275 46.7,91.675 47.675,91.675 49.65,89.7 63.075,89.7 65.4,92.025 v1(70,92.025) ; 27.425,41.05 29.35,39.125 30.95,39.125 31.725,38.35 33,38.35 U25.B4@33.3,38.05
  Bottom Layer w0.12: v1(13.925,91.05) 17.475,91.05 19.575,93.15 ; v1(13.928,41.75) 15.136,41.75 16.011,42.625 16.653,42.625 17.003,42.975 18.092,42.975 18.172,42.895 23.78,42.895 24.575,42.1 26.375,42.1 27.425,41.05 ; R55.1@69.95,104.1 v1(70.9,104.1)
PI4: U25.H14
PJ1: TP8.1 U25.G4 | length 19.1
  Signal Layer 3 w0.1: v1(34.925,53.275) 34.925,49.35 36.95,47.325 36.95,38.4 v3(37.125,38.225)
  Signal Layer 4 w0.1: v2(36.9,38.45) v3(37.125,38.225)
  Bottom Layer w0.1: TP8.1@34.353,51.304 34.353,52.703 v1(34.925,53.275)
  Bottom Layer w0.12: v2(36.9,38.45) U25.G4@37.3,38.05
PJ2: TP18.1 U25.D2 | length 15.3
  Bottom Layer w0.1: TP18.1@27.553,49.604 27.574,49.604 29.427,47.75 33.4,47.75 33.825,47.325 33.825,45.925 33.825,42.375 34.6,41.6 34.6,39.95 U25.D2@34.9,39.65
PJ3: TP11.1 U25.D1 | length 16.1
  Bottom Layer w0.1: TP11.1@27.553,51.304 28.428,50.429 28.428,49.222 29.7,47.95 33.483,47.95 34.025,47.408 34.025,45.925 34.025,42.55 34.9,41.675 U25.D1@34.9,40.45
PJ4: TP17.1 U25.E3 | length 15.1
  Bottom Layer w0.1: TP17.1@29.253,49.604 30.707,48.15 33.566,48.15 33.665,48.051 34.25,47.466 34.25,45.925 34.25,42.75 35.2,41.8 35.2,39.35 U25.E3@35.7,38.85
PJ5: TP9.1 U25.F3 | length 15.6
  Bottom Layer w0.1: TP9.1@30.953,51.304 30.953,51.296 31.86,50.388 31.86,49.265 32.375,48.75 33.814,48.75 34.875,47.689 34.875,43.313 36,42.188 36,39.35 U25.F3@36.5,38.85
PJ6: TP10.1 U25.E2 | length 15.9
  Bottom Layer w0.1: TP10.1@29.253,51.304 30.175,50.383 30.175,49.15 30.975,48.35 33.649,48.35 33.948,48.051 34.475,47.524 34.475,45.925 34.475,42.972 35.4,42.047 35.4,39.95 U25.E2@35.7,39.65
PJ7: TP16.1 U25.E1 | length 12.1
  Bottom Layer w0.1: TP16.1@30.953,49.604 32.007,48.55 33.731,48.55 33.931,48.35 34.675,47.606 34.675,45.925 34.675,43.125 35.7,42.1 U25.E1@35.7,40.45
PJ8: TP12.1 U25.F2 | length 12.8
  Bottom Layer w0.1: TP12.1@32.653,50.429 32.653,49.422 33.125,48.95 33.897,48.95 35.075,47.772 35.075,43.73 36.2,42.605 36.2,39.95 U25.F2@36.5,39.65
PJ9: TP7.1 U25.H4 | length 16.8
  Signal Layer 3 w0.1: v1(36.25,52.25) 36.25,49.3 37.725,47.825 37.725,38.775 v3(38.275,38.225)
  Signal Layer 4 w0.1: v3(38.275,38.225) v2(38.5,38.45)
  Bottom Layer w0.1: TP7.1@36.053,51.304 36.053,52.016 36.25,52.214 v1(36.25,52.25)
  Bottom Layer w0.12: U25.H4@38.1,38.05 v2(38.5,38.45)
PJ10: TP15.1 U25.F1 | length 10
  Bottom Layer w0.1: TP15.1@34.353,49.604 35.275,48.682 35.275,43.95 36.5,42.725 U25.F1@36.5,40.45
PJ11: TP14.1 U25.G3 | length 18.4
  Signal Layer 3 w0.1: v1(35.55,52.525) 35.55,49.425 37.3,47.675 v3(37.3,38.85)
  Signal Layer 4 w0.1: v2(37.08,39.06) 37.085,39.06 37.295,38.85 v3(37.3,38.85)
  Bottom Layer w0.1: v1(35.55,52.525) 35.275,52.25 35.275,50.382 TP14.1@36.053,49.604 ; v2(37.08,39.06) 37.085,39.06 37.295,38.85 v3(37.3,38.85)
SAI1.SD_B: U5.29 U25.C3 | length 61.1
  Top Layer w0.12: v1(26.575,87.425) 28.925,89.775 28.925,91 30.575,92.65 U5.29@31.225,92.65
  Signal Layer 3 w0.09: v3(26.375,43.725) 26.373,43.727 26.373,87.176 26.575,87.378 v1(26.575,87.425)
  Signal Layer 4 w0.12: v3(26.375,43.725) v2(26.65,43.45)
  Bottom Layer w0.1: 32.1,39.626 32.376,39.35 33.6,39.35 U25.C3@34.1,38.85
  Bottom Layer w0.12: v2(26.65,43.45) 27.375,43.45 30.3,40.525 31.201,40.525 32.1,39.626
SDMMC1.CK: R114.1 U25.C10 U26.M6 U27.M6 | length 45
  Signal Layer 3 w0.09: v3(17.025,24.273) 17.025,25.575 17.225,25.775 18.175,25.775 18.6,26.2 22.075,26.2 22.15,26.275 22.15,26.55 22.075,26.625 18.45,26.625 18.075,26.25 16.5,26.25 16.35,26.4 16.35,28.5 16.525,28.675 19.75,28.675 20,28.925 25.975,28.925 26.35,29.3 v3(26.35,32.425)
  Signal Layer 4 w0.1: v2(17.025,23.925) v3(17.025,24.273) ; v3(26.35,32.425) v2(26.35,32.775)
  Bottom Layer w0.08: 16.845,27.505 16.845,28.899 16.972,29.026 17.345,29.026 U27.M6@17.585,28.786
  Bottom Layer w0.1: 26.675,33.1 27.25,33.675 ; 31.474,33.75 33.6,33.75 U25.C10@34.1,33.25
  Bottom Layer w0.12: 16.845,27.505 16.75,27.41 16.75,24.2 v2(17.025,23.925) R114.1@17.025,23.5 ; v2(26.35,32.775) 27.45,33.875 31.075,33.875 31.2,33.75 31.474,33.75
SDMMC1.CMD: R113.1 U25.B9 U26.M5 U27.M5 | length 43.5
  Signal Layer 3 w0.09: v3(18.1,24.273) 18.481,24.273 18.526,24.273 18.623,24.37 18.623,25.584 18.721,25.681 18.916,25.681 19.013,25.584 19.013,24.258 19.111,24.161 19.306,24.161 19.403,24.258 19.403,25.584 19.501,25.681 19.696,25.681 19.793,25.584 19.793,24.258 19.891,24.161 20.086,24.161 20.183,24.258 20.183,25.584 20.281,25.681 20.476,25.681 20.573,25.584 20.573,24.258 20.671,24.161 20.866,24.161 20.963,24.258 20.963,25.584 21.061,25.681 21.256,25.681 21.353,25.584 21.353,24.986 21.451,24.889 21.589,24.889 21.771,25.071 23.2,26.5 25.2,26.5 26.9,28.2 26.9,33.9 26.525,34.275 v3(25.125,34.275)
  Signal Layer 4 w0.1: v2(18.1,23.925) v3(18.1,24.273) ; v3(25.125,34.275) v2(25.473,34.275)
  Bottom Layer w0.08: 17.325,27.475 17.325,28.425 17.436,28.536 17.835,28.536 U27.M5@18.085,28.786
  Bottom Layer w0.1: 31.8,34.45 32.675,34.45 33.075,34.05 U25.B9@33.3,34.05
  Bottom Layer w0.12: 17.325,27.475 17.15,27.3 17.15,26.6 18.1,25.65 R113.1@18.1,23.5 ; v2(25.473,34.275) 25.973,34.775 27.425,34.775 31.475,34.775 31.8,34.45
SDMMC1.D0: R97.1 U25.A14 U26.A3 U27.A3 | length 40.6
  Signal Layer 3 w0.09: v3(20.575,37.677) 19.448,36.55 17.925,36.55 16.225,34.85 16.225,31.45 15.675,30.9 15.675,25.241 17.166,23.75 21,23.75 23.375,26.125 v3(25.475,26.125)
  Signal Layer 4 w0.1: v3(20.575,37.677) v2(20.575,38.025) ; v3(25.475,26.125) v2(25.925,26.125)
  Bottom Layer w0.12: U27.A3@19.085,34.286 19.085,34.96 20.575,36.45 v2(20.575,38.025) R97.1@20.575,38.475 ; v2(25.925,26.125) 27.8,26.125 30.2,28.525 30.975,28.525 U25.A14@32.5,30.05
SDMMC1.D1: R99.1 U25.C14 U26.A4 U27.A4 | length 43.1
  Signal Layer 3 w0.09: v3(18.45,37.702) 18.023,37.275 16.45,37.275 15.875,36.7 15.875,31.625 15.325,31.075 15.325,25.15 17.075,23.4 21.15,23.4 23.425,25.675 26.973,25.675 v3(27.1,25.548)
  Signal Layer 4 w0.1: v3(18.45,37.702) v2(18.45,38.05) ; v2(27.1,25.2) v3(27.1,25.548)
  Bottom Layer w0.12: R99.1@18.45,38.475 v2(18.45,38.05) 18.45,35.775 18.585,35.64 U27.A4@18.585,34.286 ; v2(27.1,25.2) 30.125,25.2 31.775,26.85 31.775,27.793 32.342,28.36 33.06,28.36 33.7,29 33.7,29.65 U25.C14@34.1,30.05
SDMMC1.D2: R100.1 U25.A10 U26.A5 U27.A5 | length 42.7
  Signal Layer 3 w0.09: v3(17.375,37.702) 16.148,37.702 16.05,37.8 16.05,37.975 16.14,38.065 17.865,38.065 17.963,38.163 17.963,38.313 17.85,38.425 14.475,38.425 14.1,38.05 14.1,36.775 14.025,36.7 13.85,36.7 13.75,36.8 13.75,38.2 14.35,38.8 18.85,38.8 19.088,38.563 19.088,37.638 19.375,37.35 19.675,37.35 20.375,38.05 20.875,38.05 21.1,37.825 21.1,32.325 21.9,31.525 v3(24.85,31.525)
  Signal Layer 4 w0.1: v3(17.375,37.702) v2(17.375,38.05) ; v3(24.85,31.525) v2(25.198,31.525)
  Bottom Layer w0.1: 31.45,32.825 31.875,33.25 32,33.25 U25.A10@32.5,33.25
  Bottom Layer w0.12: R100.1@17.375,38.475 v2(17.375,38.05) 17.375,36.15 18.085,35.44 U27.A5@18.085,34.286 ; v2(25.198,31.525) 26.45,31.525 27.75,32.825 31.45,32.825
SDMMC1.D3: R95.1 U25.B10 U26.B2 U27.B2 | length 44
  Signal Layer 3 w0.09: v3(22.7,37.702) 22.7,37.605 22.603,37.507 21.865,37.507 21.768,37.41 21.768,37.215 21.865,37.117 22.7,37.117 23.535,37.117 23.632,37.02 23.632,36.825 23.535,36.727 22.7,36.727 21.865,36.727 21.768,36.63 21.768,36.435 21.865,36.337 22.7,36.337 23.508,36.337 23.605,36.24 23.605,36.045 23.508,35.947 22.7,35.947 21.865,35.947 21.768,35.85 21.768,35.655 21.865,35.557 22.7,35.557 23.535,35.557 23.632,35.46 23.632,35.265 23.535,35.167 22.7,35.167 21.865,35.167 21.768,35.07 21.768,34.875 21.865,34.777 22.7,34.777 23.535,34.777 23.632,34.68 23.632,34.485 23.535,34.387 22.7,34.387 21.865,34.387 21.768,34.29 21.768,34.095 21.865,33.997 22.7,33.997 23.535,33.997 23.632,33.9 23.632,33.705 23.535,33.607 22.7,33.607 21.865,33.607 21.768,33.51 21.768,33.315 21.865,33.217 22.7,33.217 23.535,33.217 23.632,33.12 23.632,32.925 23.535,32.827 22.798,32.827 22.7,32.73 22.7,32.7 22.7,32.41 23.16,31.95 v3(25.65,31.95)
  Signal Layer 4 w0.1: v3(22.7,37.702) v2(22.7,38.05) ; v3(25.65,31.95) v2(25.998,31.95)
  Bottom Layer w0.08: U27.B2@19.585,33.786 19.835,34.036 19.835,34.485
  Bottom Layer w0.1: 31.325,33.225 31.65,33.55 31.75,33.55 33,33.55 U25.B10@33.3,33.25
  Bottom Layer w0.12: 19.835,34.485 22.7,37.35 v2(22.7,38.05) R95.1@22.7,38.475 ; v2(25.998,31.95) 26.25,31.95 27.525,33.225 31.325,33.225
SDMMC1.D4: R96.1 U25.C6 U26.B3 U27.B3 | length 44.9
  Signal Layer 3 w0.09: v3(21.625,37.677) 21.923,37.975 25.625,37.975 25.725,38.075 25.725,38.22 25.62,38.325 21.195,38.325 21.1,38.42 21.1,38.6 21.175,38.675 25.955,38.675 26.2,38.43 26.2,34.8 26.275,34.725 26.55,34.725 26.65,34.825 26.65,36.931 26.77,37.05 26.925,37.05 27.025,36.95 27.025,34.325 27.15,34.2 27.3,34.2 27.4,34.3 27.4,38.7 27.05,39.05 v3(26.35,39.05)
  Signal Layer 4 w0.1: v3(21.625,37.677) v2(21.625,38.025) ; v3(26.35,39.05) v2(26.575,38.825)
  Bottom Layer w0.08: U27.B3@19.085,33.786 19.346,34.046 19.346,34.186 ; 19.345,34.186 19.345,34.62
  Bottom Layer w0.1: 32.07,36.975 32.275,36.975 32.3,36.95 33.6,36.95 U25.C6@34.1,36.45
  Bottom Layer w0.12: 19.345,34.62 19.9,35.175 21.625,36.9 v2(21.625,38.025) R96.1@21.625,38.475 ; v2(26.575,38.825) 28.225,37.175 29.925,37.175 30.125,36.975 32.07,36.975
SDMMC1.D5: R98.1 U25.C5 U26.B4 U27.B4 | length 45.8
  Signal Layer 3 w0.09: v3(19.525,37.702) 19.525,39.775 19.725,39.975 19.823,39.975 19.92,39.878 19.92,39.39 20.018,39.293 20.213,39.293 20.31,39.39 20.31,39.975 20.31,40.733 20.408,40.83 20.603,40.83 20.7,40.733 20.7,39.975 20.7,39.39 20.798,39.293 20.993,39.293 21.09,39.39 21.09,39.975 21.09,40.733 21.188,40.83 21.383,40.83 21.48,40.733 21.48,39.975 21.48,39.39 21.578,39.293 21.773,39.293 21.87,39.39 21.87,39.975 21.87,40.733 21.968,40.83 22.163,40.83 22.26,40.733 22.26,39.975 22.26,39.39 22.358,39.293 22.553,39.293 22.65,39.39 22.65,39.975 22.65,40.733 22.748,40.83 22.943,40.83 23.04,40.733 23.04,39.975 23.04,39.477 23.138,39.379 23.333,39.379 23.43,39.477 23.43,39.975 23.43,40.733 23.528,40.83 23.723,40.83 23.82,40.733 23.82,39.975 23.82,39.39 23.918,39.293 24.113,39.293 24.21,39.39 24.21,39.975 24.21,40.733 24.308,40.83 24.503,40.83 24.6,40.733 24.6,39.975 24.6,39.39 24.698,39.293 24.893,39.293 24.99,39.39 24.99,39.975 24.99,40.733 25.088,40.83 25.283,40.83 25.38,40.733 25.38,39.975 25.38,39.39 25.478,39.293 25.673,39.293 25.77,39.39 25.77,39.975 25.77,40.733 25.868,40.83 26.063,40.83 26.16,40.733 26.16,40.073 26.258,39.975 26.45,39.975 v3(27.275,39.975)
  Signal Layer 4 w0.1: v3(19.525,37.702) v2(19.525,38.05) ; v3(27.275,39.975) v2(27.5,39.75)
  Bottom Layer w0.08: U27.B4@18.585,33.786 18.846,34.046 18.846,34.186 18.845,34.975
  Bottom Layer w0.1: 31.961,37.875 32.175,37.875 32.3,37.75 33.6,37.75 U25.C5@34.1,37.25
  Bottom Layer w0.12: 18.845,34.975 18.845,35.27 19.525,35.95 v2(19.525,38.05) R98.1@19.525,38.475 ; v2(27.5,39.75) 28.85,38.4 30.6,38.4 31.125,37.875 31.961,37.875
SDMMC1.D6: R101.1 U25.C15 U26.B5 U27.B5 | length 42.6
  Signal Layer 3 w0.09: v3(15.675,37.702) 15.52,37.547 15.52,31.845 14.975,31.3 14.975,25.125 17.025,23.075 21.375,23.075 23.525,25.225 v3(26.175,25.225)
  Signal Layer 4 w0.1: v3(15.675,37.702) v2(15.675,38.05) ; v3(26.175,25.225) v2(26.525,25.225)
  Bottom Layer w0.08: 17.825,34.186 17.825,34.046 U27.B5@18.085,33.786 ; 17.825,34.186 17.825,34.975
  Bottom Layer w0.12: R101.1@15.675,38.475 15.675,37.125 17.825,34.975 ; v2(26.525,25.225) 27.025,24.725 30.225,24.725 32.193,26.693 32.193,27.605 32.535,27.948 33.198,27.948 34.1,28.85 U25.C15@34.1,29.25
SDMMC1.D7: R102.1 U25.B15 U26.B6 U27.B6 | length 42.1
  Signal Layer 3 w0.09: v3(14.625,37.702) 14.625,25.025 16.925,22.725 21.6,22.725 23.652,24.777 v3(25.749,24.777)
  Signal Layer 4 w0.1: v3(14.625,37.702) v2(14.625,38.05) ; v3(25.749,24.777) v2(25.749,25.125)
  Bottom Layer w0.08: 17.335,34.325 17.335,34.036 U27.B6@17.585,33.786
  Bottom Layer w0.1: 17.184,34.615 17.335,34.463 17.335,34.325
  Bottom Layer w0.12: R102.1@14.625,38.475 14.625,37.174 17.184,34.615 ; v2(25.749,25.125) 26.349,25.725 30.035,25.725 31.253,26.942 31.253,27.975 32.007,28.73 32.78,28.73 U25.B15@33.3,29.25
SPI_CLK: CN2.24 SB16.1 SB17.1 | length 33.6
  Top Layer w0.12: SB17.1@34.85,62.3 34.85,63 35.075,63.225 49.616,63.225 53.175,66.784 53.175,72.4 53.525,72.75 53.525,74.205 53.259,74.471 SB16.1@52.5,74.471 52.5,76.65 51.889,77.261 CN2.24@51.889,78.54
SPI_D/CX: CN2.28 SB18.1 | length 4.6
  Top Layer w0.12: SB18.1@49.725,74.446 49.725,75.825 50.889,76.989 CN2.28@50.889,78.54
SPI_MOSI: CN2.26 SB14.1 SB19.1 | length 47.3
  Top Layer w0.12: v1(25,60.9) 27.125,60.9 27.275,60.75 SB19.1@27.275,60.25 ; v1(25,64.65) 25.375,65.025 28.325,65.025 29.4,63.95 49.1,63.95 50.8,65.65 50.8,73.471 50.675,73.596 50.675,76.046 51.1,76.471 SB14.1@51.55,76.471 51.55,76.508 51.466,76.592 51.466,76.624 51.389,76.701 CN2.26@51.389,78.54
  Signal Layer 3 w0.09: v1(25,60.9) v1(25,64.65)
SPI_USART_CS: CN2.22 SB15.1 | length 2.7
  Top Layer w0.12: CN2.22@52.389,78.54 52.389,77.161 52.9,76.65 53.271,76.65 SB15.1@53.45,76.471
STLK_MCO: C82.2 R42.2 SB28.1 | length 54.5
  Top Layer w0.1: R42.2@67.25,17.575 67.25,21.875
  Top Layer w0.12: SB28.1@44.55,46.5 47.35,43.7 47.35,41.485 48.725,40.11 49.78,40.11 50.535,40.865 50.535,42.045 51.325,42.835 53.175,42.835 56.085,39.925 56.085,35.445 55.445,34.805 55.445,34.105 53.835,32.495 53.835,31.695 54.705,30.825 63.21,30.825 63.72,30.315 63.72,29.81 65.785,27.745 66.54,27.745 68.325,25.96 68.325,23.425 67.25,22.35 67.25,21.875 ; R42.2@67.25,17.575 C82.2@68.075,17.575
STLK_SWCLK: CN12.2 U10.A14 U16.1 | length 30.7
  Top Layer w0.12: CN12.2@53.655,1.875 53.663,1.883 U16.1@53.663,3.875 v1(53.663,7.25) ; U10.A14@64.4,19.35 64.925,19.875 v1(64.925,20.2)
  Signal Layer 3 w0.09: v1(54.025,20.2) v1(64.925,20.2)
  Bottom Layer w0.1: v1(53.663,7.25) 54.275,7.863 54.275,14.325 54.025,14.575 v1(54.025,20.2)
STLK_SWDIO: CN12.4 U10.A15 U17.1 | length 37.5
  Top Layer w0.12: v1(54.475,7.25) 54.475,6.575 56.35,4.7 60.05,4.7 61.175,3.575 61.175,2.2 60.838,1.863 U17.1@60.5,1.863 58.748,1.863 CN12.4@58.735,1.875 ; U10.A15@65.05,19.35 65.575,19.875 v1(65.575,20.2)
  Signal Layer 3 w0.09: v1(54.475,19.825) 65.2,19.825 v1(65.575,20.2)
  Bottom Layer w0.1: v1(54.475,7.25) v1(54.475,19.825)
STLK_VCP_RX: R122.2 U10.C10 U31.3 | length 6.9
  Top Layer w0.1: U10.C10@61.8,18.05 62.125,17.725 62.125,16.325 62.325,16.125 v1(62.325,14.9)
  Bottom Layer w0.1: R122.2@61.025,16.95 62.275,16.95 62.625,16.6 U31.3@62.625,15.875 62.625,15.2 v1(62.325,14.9)
STLK_VCP_TX: R110.1 U10.A7 | length 14.2
  Top Layer w0.1: U10.A7@59.85,19.35 59.85,24.25 60.625,25.025 67.25,25.025 v1(67.85,25.625)
  Bottom Layer w0.1: v1(67.85,25.625) R110.1@68.6,25.625
T.JTDI: CN3.8 CN11.10 SB42.1 U33.1 | length 108
  Top Layer w0.12: SB42.1@25.525,28.5 25.725,28.3 v1(25.725,24.3) ; v1(26.2,17.1) 26.2,16.15 35.925,6.425 46.975,6.425 47.625,7.075 47.625,16.025 v1(47.125,16.525) ; CN3.8@87.305,17.39 v1(88.095,17.39)
  Signal Layer 3 w0.09: v1(25.725,24.3) 25.725,21.685 26.46,20.95 26.46,19.61 26.225,19.375 26.225,17.125 v1(26.2,17.1) ; v1(47.125,16.525) 47.425,16.825 62.9,16.825 63.02,16.705 63.578,16.705 63.588,16.715 65.785,16.715 66.5,16 70.25,16 v1(70.675,16.425) ; v3(71.218,15.9) 76.257,15.9 77.157,16.8 87.505,16.8 v1(88.095,17.39)
  Signal Layer 4 w0.1: v3(71.218,15.9) v2(71.614,15.9)
  Bottom Layer w0.12: CN11.10@60.695,23.793 60.695,21.89 61.02,21.565 65.86,21.565 70.15,17.275 70.8,17.275 71.2,16.875 U33.1@71.2,15.9 ; v1(70.675,16.425) 70.675,16 U33.1@70.775,15.9 U33.1@71.2,15.9 ; v2(71.614,15.9) U33.1@71.2,15.9
T.SWCLK: CN3.4 CN11.6 R126.1 U25.A12 U33.4 | length 104.8
  Top Layer w0.12: v1(69.075,15.175) 70.075,16.175 70.075,17.475 v1(70.075,21.65) ; v1(85.235,16.13) CN3.4@86.025,16.13
  Signal Layer 3 w0.09: v3(32.675,31.475) 33.175,31.475 33.575,31.075 33.575,7.175 34.325,6.425 61.2,6.425 67.85,13.075 v3(67.85,13.642) ; v3(58.38,21.65) 62.425,21.65 62.6,21.825 67.65,21.825 69.831,21.825 70.006,21.65 v1(70.075,21.65) ; v1(69.075,15.175) 77.05,15.175 78.005,16.13 v1(85.235,16.13)
  Signal Layer 4 w0.1: v3(32.675,31.475) v2(32.9,31.25) ; v2(58.155,21.875) v3(58.38,21.65) ; v3(67.85,13.642) v2(67.85,14.037)
  Bottom Layer w0.12: U25.A12@32.5,31.65 v2(32.9,31.25) ; v2(58.155,21.875) CN11.6@58.155,23.793 ; v2(67.85,14.037) R126.1@67.85,14.6 U33.4@69.075,14.6 v1(69.075,15.175)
